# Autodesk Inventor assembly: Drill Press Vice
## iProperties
Created: 2002-02
Part Number: Drill Press Vice
Document SubType Name: Assembly
Designer: ***
Control State: 0
Master: False
Checked Out: False
Shininess: 64.0
Length Units: 11269
Angle Units: 11279
Time Units: 11290
Mass Units: 11283
Length Display Precision: 3
Angle Display Precision: 2
Density: 0.0
Volumn: 0.0
Area: 0.0
PropertySet Name: Model Information
Author: ***
